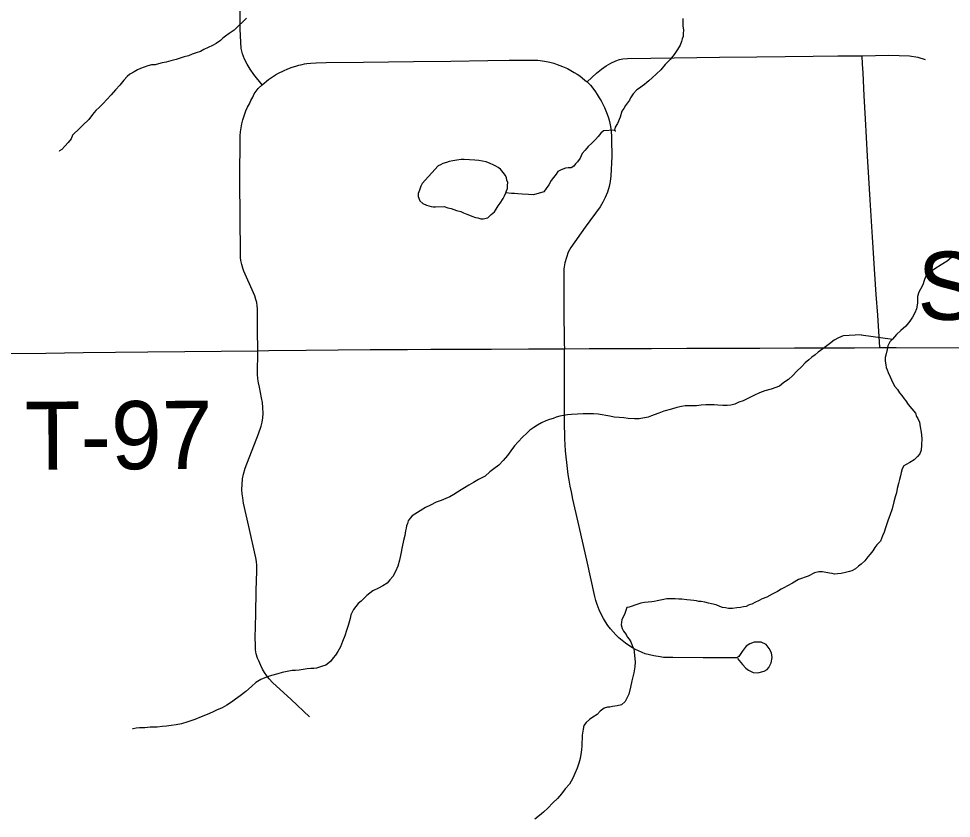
# Model space of a CAD drawing. Extents: x 103424 to 286016, y 38711 to 110967.
# Drawn here: x 108708 to 112838, y 81319 to 84863 of the extents above; entities that cross this region are included whole.
import ezdxf

# ---------------------------------------------------------------- set-up
doc = ezdxf.new("R2010")
doc.units = 0
for name, color, linetype in [('GM_X_Minor_Lake', 7, 'Continuous'), ('GM_X_Minor_River', 7, 'Continuous'), ('GM_X_Township_Road', 7, 'Continuous'), ('GM_X_Township_Road_Text', 7, 'Continuous')]:
    doc.layers.add(name, color=color, linetype=linetype)

msp = doc.modelspace()

# ---------------------------------------------------------------- linework, layer by layer
at = {"layer": 'GM_X_Minor_Lake'}
for points in [[(110495, 84132.8), (110488.3, 84120.7), (110482.5, 84102.5), (110476.6, 84088.3), (110476.7, 84074.1), (110485, 84056), (110497.3, 84044.1), (110513.5, 84036.1), (110533.8, 84030.3), (110543.9, 84028.4), (110554, 84028.4), (110592.4, 84030.9), (110608.6, 84025), (110622.8, 84021.1), (110634.9, 84017.1), (110647.1, 84013.2), (110665.3, 84007.3), (110677.5, 84001.4), (110691.7, 83995.5), (110703.9, 83991.6), (110714, 83987.6), (110730.3, 83981.7), (110740.4, 83979.8), (110754.6, 83975.9), (110764.7, 83976), (110784.8, 83980.3), (110800.8, 83994.6), (110814.8, 84006.8), (110822.7, 84019), (110830.6, 84033.3), (110840.6, 84045.5), (110852.5, 84065.8), (110858.4, 84078), (110864.3, 84090.2), (110868.2, 84100.3), (110872.2, 84110.4), (110872, 84122.5), (110873.9, 84136.7), (110869.7, 84146.8), (110867.6, 84156.8), (110863.4, 84166.9), (110853.2, 84180.9), (110840.9, 84195), (110830.7, 84202.9), (110820.5, 84208.9), (110808.3, 84214.8), (110796.2, 84220.8), (110777.9, 84228.7), (110761.7, 84230.5), (110745.5, 84234.4), (110727.3, 84236.2), (110680.8, 84237.8), (110666.7, 84237.7), (110648.5, 84235.5), (110630.4, 84233.2), (110614.3, 84229.1), (110602.2, 84224.9), (110586.1, 84220.7), (110576.1, 84214.5), (110566, 84210.4), (110495, 84132.8)], [(110840.6, 84045.5), (110852.5, 84065.8), (110858.4, 84078), (110864.3, 84090.2), (110868.2, 84100.3), (110872.2, 84110.4), (110872, 84122.5), (110873.9, 84136.7), (110869.7, 84146.8), (110867.6, 84156.8), (110863.4, 84166.9), (110853.2, 84180.9), (110840.9, 84195), (110830.7, 84202.9), (110820.5, 84208.9), (110808.3, 84214.8), (110796.2, 84220.8), (110777.9, 84228.7), (110761.7, 84230.5), (110745.5, 84234.4), (110727.3, 84236.2), (110680.8, 84237.8), (110666.7, 84237.7), (110648.5, 84235.5), (110630.4, 84233.2), (110614.3, 84229.1), (110602.2, 84224.9), (110586.1, 84220.7), (110576.1, 84214.5), (110566, 84210.4), (110495, 84132.8)], [(110495, 84132.8), (110488.3, 84120.7), (110482.5, 84102.5), (110476.6, 84088.3), (110476.7, 84074.1), (110485, 84056), (110497.3, 84044.1), (110513.5, 84036.1), (110533.8, 84030.3), (110543.9, 84028.4), (110554, 84028.4), (110592.4, 84030.9), (110608.6, 84025), (110622.8, 84021.1), (110634.9, 84017.1), (110647.1, 84013.2), (110665.3, 84007.3), (110677.5, 84001.4), (110691.7, 83995.5), (110703.9, 83991.6), (110714, 83987.6), (110730.3, 83981.7), (110740.4, 83979.8), (110754.6, 83975.9), (110764.7, 83976), (110784.8, 83980.3), (110800.8, 83994.6), (110814.8, 84006.8), (110822.7, 84019), (110830.6, 84033.3), (110840.6, 84045.5)]]:
    msp.add_lwpolyline(points, dxfattribs=at)
at = {"layer": 'GM_X_Minor_River'}
for points in [[(109716.2, 84864.5), (109700.2, 84848.1), (109682.3, 84831.8)], [(111649, 84863.6), (111649.2, 84847.5), (111649.4, 84831.3), (111651.7, 84811.1), (111649.8, 84797), (111650, 84782.8), (111646.1, 84772.7), (111642.2, 84760.5), (111636.3, 84744.3), (111624.4, 84726), (111610.5, 84703.6), (111592.6, 84681.3), (111570.6, 84658.8), (111550.7, 84636.4), (111532.7, 84618), (111512.8, 84599.7), (111498.8, 84587.4), (111488.8, 84579.2), (111478.8, 84571), (111468.8, 84562.8), (111456.7, 84554.6), (111444.7, 84546.4), (111428.7, 84530.1), (111416.8, 84511.8), (111412.9, 84501.7), (111403, 84489.5), (111395, 84477.3), (111387.1, 84465.1), (111379.2, 84452.9), (111371.4, 84426.5), (111359.6, 84398.1), (111349.7, 84381.9), (111345.8, 84367.7), (111349.9, 84365.7), (111351.9, 84365.7)], [(109682.3, 84831.8), (109662.3, 84811.4), (109640.2, 84797), (109624.2, 84784.8), (109612.2, 84776.6), (109602.2, 84766.4), (109582.2, 84752), (109566.1, 84743.8), (109528, 84725.2), (109513.9, 84717), (109493.8, 84710.7), (109475.7, 84704.5), (109459.6, 84698.3), (109441.5, 84694), (109423.4, 84687.8), (109405.3, 84681.6), (109381.1, 84675.3), (109361, 84669), (109342.9, 84666.8), (109326.8, 84662.6), (109312.7, 84658.4), (109296.5, 84658.2), (109280.4, 84654), (109264.3, 84647.8), (109248.2, 84641.6), (109234.2, 84635.4), (109220.1, 84627.2), (109200, 84616.9), (109188, 84606.7), (109174.1, 84590.4), (109156.2, 84568), (109136.2, 84547.6), (109118.3, 84525.2), (109098.3, 84504.8), (109082.4, 84486.4), (109066.4, 84470.1), (109050.4, 84455.8), (109034.5, 84437.5), (109018.6, 84415.1), (108992.6, 84390.6), (108970.7, 84368.1), (108954.7, 84355.8), (108946.7, 84345.7), (108940.8, 84329.4), (108926.9, 84313.2), (108912.9, 84296.8), (108899, 84282.6), (108888.9, 84276.4), (108886.9, 84274.4)], [(111345.8, 84367.7), (111297.4, 84365.2), (111285.4, 84355), (111273.4, 84340.7), (111261.5, 84326.4), (111245.5, 84310.1), (111229.5, 84295.8), (111215.6, 84279.5), (111203.6, 84265.3), (111193.7, 84245), (111181.8, 84228.7), (111173.9, 84218.5), (111165.9, 84208.3), (111153.8, 84202.1), (111141.7, 84202), (111129.6, 84199.9), (111117.6, 84195.7), (111107.5, 84191.6), (111095.5, 84185.4), (111087.5, 84173.2), (111075.6, 84158.9), (111065.7, 84144.7), (111055.8, 84126.4), (111043.8, 84110.1), (111033.9, 84095.9), (110987.6, 84081.3), (110965.4, 84083.1), (110937.1, 84084.8), (110918.9, 84086.7), (110902.7, 84088.5), (110890.6, 84088.4), (110864.3, 84090.2)], [(112838.8, 83804.9), (112818.8, 83788.5), (112792.7, 83772.1), (112764.7, 83753.6), (112744.6, 83741.3), (112728.6, 83731.1), (112722.7, 83718.9), (112716.8, 83702.7), (112711, 83682.4), (112701.1, 83664.1), (112693.2, 83649.9), (112687.3, 83631.7), (112687.4, 83621.6), (112687.7, 83601.4), (112683.9, 83577.1), (112676.1, 83558.8), (112666.2, 83540.5), (112654.3, 83522.2), (112636.4, 83499.8), (112614.3, 83481.4), (112594.4, 83463.1), (112576.4, 83442.7), (112564.5, 83430.5), (112556.6, 83412.2), (112552.7, 83396), (112548.9, 83377.8), (112545.1, 83361.6), (112545.2, 83345.4), (112547.5, 83329.3), (112549.6, 83317.2), (112553.8, 83307.1), (112557.9, 83295), (112566.3, 83274.9), (112572.5, 83262.9), (112578.7, 83248.8), (112586.9, 83232.7), (112599.2, 83218.7), (112607.5, 83204.6), (112617.7, 83192.6), (112628, 83178.6), (112636.2, 83168.5), (112646.5, 83152.5), (112679.2, 83114.4), (112683.4, 83100.3), (112689.6, 83090.3), (112695.8, 83074.2), (112700.1, 83054.1), (112704.4, 83029.9), (112706.8, 83001.6), (112705.1, 82973.3), (112703.3, 82951.1), (112697.5, 82934.8), (112687.5, 82922.6), (112673.5, 82908.3), (112653.5, 82896), (112637.4, 82887.8), (112627.4, 82881.6), (112619.5, 82867.4), (112615.6, 82851.2), (112611.7, 82837), (112607.9, 82820.8), (112604.1, 82802.6), (112598.3, 82780.3), (112594.4, 82762.1), (112588.6, 82743.9), (112582.8, 82721.6), (112575.1, 82691.2), (112565.3, 82660.8), (112557.5, 82642.5), (112551.6, 82624.3), (112545.8, 82606.1), (112539.9, 82587.8), (112532, 82571.6), (112524.2, 82547.3), (112508.3, 82531)], [(112438.9, 83461.5), (112358.1, 83456.7), (112338, 83448.4), (112318, 83438.1), (112298, 83421.7), (112267.9, 83399.2), (112247.9, 83384.9), (112233.9, 83372.6), (112219.9, 83362.3), (112205.9, 83350.1), (112189.9, 83337.8), (112173.9, 83319.5), (112154, 83301.1), (112136, 83280.7), (112116, 83264.4), (112096, 83250), (112076, 83233.7), (112039.8, 83221.2), (112011.6, 83212.8), (111987.4, 83204.5), (111963.4, 83192.1), (111937.2, 83179.7), (111915.1, 83169.4), (111897, 83163.2), (111879, 83154.9), (111860.8, 83150.7), (111844.7, 83148.5), (111826.5, 83148.3), (111804.3, 83150.1), (111788.1, 83152), (111769.9, 83151.8), (111749.8, 83151.6), (111729.6, 83149.4), (111709.4, 83147.2), (111691.2, 83147), (111675.1, 83146.8), (111658.9, 83146.7), (111642.8, 83144.5), (111622.6, 83140.2), (111598.5, 83131.9), (111564.3, 83123.5), (111542.1, 83115.2), (111522.1, 83106.9), (111510, 83102.7), (111495.9, 83096.5), (111455.6, 83090.1), (111435.4, 83089.9), (111407.1, 83091.6), (111386.9, 83093.4), (111366.7, 83095.2), (111344.4, 83097), (111326.2, 83100.9), (111308, 83104.8), (111291.8, 83106.6), (111273.6, 83110.5), (111253.4, 83112.3), (111231.2, 83112.1), (111206.9, 83111.8), (111182.7, 83109.6), (111156.5, 83109.3), (111138.3, 83107.1), (111120.2, 83104.9), (111104.1, 83100.7), (111088, 83096.5), (111073.9, 83090.3), (111057.8, 83086.1), (111041.7, 83079.9), (111023.6, 83071.6), (111005.6, 83061.3), (110989.5, 83051.1), (110971.5, 83038.8), (110957.5, 83026.5), (110939.5, 83008.1), (110919.6, 82987.7), (110903.6, 82969.4), (110887.7, 82947), (110871.8, 82926.7), (110853.9, 82904.3), (110833.9, 82883.9), (110811.9, 82867.5), (110793.9, 82855.2), (110773.9, 82834.8), (110743.8, 82820.3), (110721.7, 82808), (110701.7, 82795.7), (110681.6, 82783.3), (110667.6, 82775.1), (110651.5, 82764.9), (110635.5, 82754.6), (110617.4, 82744.3), (110599.4, 82736.1), (110579.2, 82727.8), (110557.1, 82719.5), (110531, 82707.1)], [(112438.9, 83461.5), (112576.4, 83442.7)], [(110531, 82707.1), (110508.9, 82696.8), (110450.8, 82659.8), (110440.8, 82649.6), (110432.9, 82637.4), (110429, 82625.3), (110425, 82615.1), (110423.1, 82605), (110421.3, 82592.9), (110417.5, 82572.6), (110411.7, 82550.4), (110405.9, 82522), (110400.2, 82491.7), (110394.5, 82463.3), (110386.7, 82437), (110376.9, 82412.7), (110365, 82390.3), (110351.1, 82376), (110339.1, 82361.8), (110321.1, 82349.5), (110301, 82339.2), (110276.9, 82326.8), (110262.9, 82316.6), (110248.9, 82306.3), (110238.9, 82296.1), (110224.9, 82281.8), (110210.9, 82271.6), (110201, 82257.4), (110191, 82245.2), (110185.1, 82233), (110179.2, 82220.8), (110175.3, 82204.6), (110167.6, 82174.2), (110159.8, 82151.9), (110152, 82127.6), (110142.2, 82103.3), (110132.4, 82078.9), (110120.5, 82058.6), (110110.6, 82042.3), (110100.6, 82030.1), (110088.7, 82013.8), (110068.7, 81997.5), (110052.6, 81993.3), (110026.4, 81984.9), (110014.3, 81982.8), (110002.2, 81982.7), (109986.1, 81982.5), (109967.9, 81978.3), (109949.8, 81976.1), (109933.6, 81973.9), (109919.5, 81973.8), (109875.2, 81965.2), (109855.1, 81959), (109826.9, 81952.6), (109804.7, 81944.3), (109780.6, 81934), (109758.5, 81921.6), (109738.6, 81903.3), (109714.6, 81880.8), (109688.5, 81862.4), (109668.5, 81848), (109650.5, 81833.7), (109630.4, 81821.4), (109608.4, 81809), (109584.3, 81798.7), (109566.2, 81790.5), (109542.1, 81780.1), (109515.9, 81769.7), (109487.8, 81757.3), (109457.6, 81746.9), (109429.4, 81738.6), (109405.3, 81734.3), (109383.1, 81730), (109362.9, 81727.8), (109342.8, 81725.6), (109320.6, 81723.3), (109290.3, 81723), (109266.1, 81720.8), (109243.8, 81720.6), (109227.7, 81718.4), (109215.6, 81716.2), (109211.6, 81716.2)], [(112508.3, 82531), (112498.3, 82518.7), (112490.4, 82504.5), (112478.5, 82490.3), (112468.5, 82478), (112454.6, 82459.7), (112438.6, 82445.4), (112426.6, 82437.2), (112412.6, 82425), (112396.5, 82416.7), (112386.5, 82412.6), (112368.3, 82408.4), (112350.2, 82404.1), (112334.1, 82402), (112319.9, 82401.8), (112309.8, 82403.7), (112297.7, 82405.6), (112267.3, 82411.4), (112251.2, 82411.2), (112231, 82407), (112202.9, 82392.6), (112160.7, 82378), (112134.6, 82361.6), (112112.5, 82349.2), (112096.5, 82341), (112084.4, 82334.8), (112068.4, 82324.5), (112044.3, 82312.2), (112020.2, 82299.8), (112000.1, 82291.5), (111984, 82283.3), (111970, 82277.1), (111953.9, 82268.9), (111941.8, 82264.7), (111929.8, 82258.5), (111917.7, 82256.4), (111903.6, 82254.2), (111887.5, 82252), (111869.3, 82249.8), (111851.1, 82249.7), (111837, 82251.5), (111824.8, 82253.4), (111812.7, 82257.3), (111796.4, 82265.3), (111776.2, 82269.1), (111762, 82273), (111745.8, 82276.9), (111729.6, 82280.8), (111719.5, 82280.7), (111709.4, 82282.6), (111697.2, 82284.5), (111683.1, 82286.3), (111666.9, 82288.2), (111644.7, 82290), (111630.5, 82289.9), (111614.3, 82291.7), (111596.2, 82291.5), (111578, 82291.4), (111557.9, 82287.1), (111535.7, 82282.9), (111521.6, 82280.7), (111511.5, 82278.6), (111479.2, 82276.2), (111463.1, 82272), (111449, 82267.8), (111436.9, 82263.7), (111424.9, 82259.5), (111410.8, 82255.3), (111400.7, 82253.2), (111391, 82222.8), (111379.1, 82200.5), (111375.4, 82176.2), (111379.6, 82160.1), (111385.8, 82148), (111398.1, 82134), (111402.2, 82124), (111410.4, 82113.9), (111418.6, 82101.9), (111424.9, 82085.8), (111431.1, 82069.7), (111437.8, 82013.2), (111436.1, 81991), (111432.3, 81964.7), (111422.7, 81928.2), (111416.9, 81899.9), (111409.2, 81869.5), (111399.4, 81849.2), (111393.4, 81837), (111377.4, 81822.7), (111357.3, 81818.5), (111337.2, 81814.2), (111325.1, 81812.1), (111315, 81812), (111300.9, 81807.8), (111282.9, 81793.5), (111268.9, 81779.2), (111250.9, 81766.9), (111234.8, 81756.7), (111220.8, 81744.4), (111210.9, 81730.1), (111207, 81713.9)], [(111207, 81713.9), (111203.3, 81687.7), (111201.8, 81641.2), (111200, 81623), (111198.1, 81612.9), (111194.4, 81584.5), (111188.6, 81564.3), (111180.8, 81542), (111170.9, 81517.7), (111161.1, 81497.4), (111147.2, 81470.9), (111127.3, 81450.6), (111111.4, 81428.2), (111093.5, 81407.8), (111073.5, 81387.4), (111051.5, 81364.9), (111031.6, 81346.6), (111013.6, 81332.3), (110993.5, 81315.9)]]:
    msp.add_lwpolyline(points, dxfattribs=at)
at = {"layer": 'GM_X_Township_Road'}
for points in [[(109785.6, 84569.9), (109748.8, 84615.5), (109733, 84639.1), (109719.4, 84660.4), (109708.6, 84683.1), (109698.4, 84706.6), (109693.7, 84730.7), (109691.5, 84757.8), (109688.5, 84816), (109688.9, 84970.8), (109689.1, 85045.5)], [(111224.6, 84582), (111266.9, 84621.4), (111288.2, 84639), (111309.8, 84653.6), (111329.4, 84664.8), (111352.4, 84675), (111367.6, 84680.8), (111382.7, 84683.8), (111404.4, 84686), (111507.3, 84687.3), (111610.1, 84688.5), (111710.8, 84690.1), (111811.6, 84691.7), (111976.6, 84693.6), (112101.4, 84695.1), (112226.2, 84696.6), (112334.3, 84697.5), (112442.3, 84698.3), (112560.1, 84700.1), (112652.7, 84698.3), (112689.7, 84692.4), (112721, 84681.1)], [(112520.4, 83405.2), (112511.5, 83549.2), (112504.9, 83639.7), (112498.3, 83730.3), (112488.3, 83895), (112478.3, 84059.8), (112472.4, 84156.5), (112466.6, 84253.1), (112457.6, 84418), (112452, 84520), (112446.5, 84622.1), (112444, 84661.1), (112442.3, 84698.3)], [(109766.5, 83391.3), (109766, 83483.9), (109765.5, 83576.5), (109764.2, 83590.5), (109761.9, 83604.4), (109758.9, 83618.1), (109753.7, 83634.8), (109748.4, 83647.9), (109705.6, 83743.8), (109700.6, 83756.9), (109695.6, 83773.8), (109692.1, 83791), (109690.6, 83804.9), (109689.8, 83821.5), (109688.5, 83982.4), (109687.2, 84143.3), (109688.3, 84343.4), (109690, 84361.2), (109692.6, 84379), (109696.1, 84396.6), (109700.4, 84413.9), (109707.7, 84436.7), (109714.3, 84453.4), (109721.6, 84469.7), (109729.9, 84485.7), (109736.2, 84500.5), (109744.5, 84514.4), (109751.4, 84529.2), (109759.7, 84541.3), (109767.9, 84552.6), (109785.6, 84569.9), (109813.9, 84593), (109832.1, 84605.1), (109845.6, 84613.4), (109859, 84620.3), (109880.8, 84632), (109899.8, 84640.7), (109918.5, 84647.2), (109935.4, 84652.4), (109948.9, 84655.9), (109963.2, 84659.4), (109973.6, 84662), (109984.1, 84663.7), (110001, 84665.4), (110025.3, 84666.4), (110069.1, 84668.1), (110234.2, 84670.1), (110345, 84671.5), (110455.8, 84672.8), (110620.9, 84674.8), (110785.9, 84676.7), (110879.3, 84677.8), (110972.7, 84678.9), (111007, 84678.5), (111027, 84675.9), (111044.8, 84672.4), (111060.4, 84669.3), (111077.3, 84664.6), (111091.6, 84659.8), (111116.4, 84650.7), (111137.6, 84641.2), (111152.8, 84633.3), (111167.6, 84624.6), (111180.2, 84616), (111192.3, 84609), (111214.9, 84590.4), (111224.6, 84582), (111239.2, 84567.4), (111250.5, 84554.4), (111261.3, 84538.3), (111269.7, 84525.7), (111278.8, 84512.1), (111287.1, 84498.1), (111294.9, 84483.7), (111301.9, 84469.1), (111308.5, 84454), (111314, 84438.7), (111319, 84423.2), (111323.3, 84407.5), (111326.8, 84391.5), (111329.6, 84375.4), (111331.6, 84359.2), (111332.8, 84342.9), (111333.3, 84326.6), (111334.3, 84251.8), (111330.3, 84166.4), (111327.3, 84140.3), (111322.1, 84118.6), (111314.7, 84093.9), (111304.3, 84070), (111294.7, 84050), (111282.2, 84029), (111216.2, 83938.5), (111153.3, 83849.1), (111141.6, 83827.4), (111132.9, 83803.9), (111126.8, 83780.5), (111121.6, 83754.5), (111121.1, 83727.1), (111122.4, 83575.5), (111123.7, 83423.8), (111124.2, 83399.6)], [(108663.4, 83378.7), (108828.4, 83380.6), (108993.5, 83382.6), (109136.4, 83384.3), (109279.3, 83386), (109444.3, 83387.8), (109605.4, 83389.6), (109766.5, 83391.3), (109815.6, 83391.9), (109980.7, 83393.6), (110122.3, 83395), (110264, 83396.4), (110429.1, 83397), (110533, 83397.4), (110636.8, 83397.8), (110800.9, 83398.4), (110964.9, 83399), (111124.2, 83399.6), (111234.3, 83400.5), (111344.3, 83401.2), (111509.4, 83401.7), (111666.9, 83402.1), (111824.4, 83402.5), (111989.5, 83402.9), (112142.8, 83403.4), (112296.2, 83403.8), (112408.3, 83404.5), (112520.4, 83405.2), (112593.1, 83405.7), (113939.6, 83404.7)], [(109996.2, 81769.8), (109914.3, 81845.6), (109832.4, 81921.4), (109817.6, 81937.4), (109806.5, 81951.2), (109796.4, 81965.7), (109787.7, 81980.8), (109779.8, 81996.5), (109771.6, 82016.8), (109765.6, 82029.2), (109760.2, 82047.8), (109757.2, 82066), (109756.1, 82088.9), (109755.5, 82118.3), (109757.7, 82223.8), (109759.9, 82329.2), (109763.2, 82415), (109762.5, 82439.9), (109760.9, 82457.1), (109758.1, 82474), (109727.6, 82612.8), (109703.1, 82716), (109699.9, 82740), (109697.9, 82757.5), (109696.9, 82775), (109699.1, 82824.3), (109703.1, 82844.3), (109711.6, 82870.3), (109770, 83022.8), (109781.5, 83056.6), (109785.8, 83075.1), (109789.5, 83093.3), (109790.9, 83113.6), (109789.2, 83139.2), (109787.5, 83162.5), (109783.8, 83182.4), (109773.9, 83230.2), (109769.3, 83248.6), (109767.3, 83266.8), (109765.9, 83287.4), (109766.5, 83391.3)], [(111891.1, 82027.9), (111912.6, 82001.5), (111926.9, 81984.1), (111939.4, 81975.6), (111960.7, 81965.8), (111980.4, 81963.6), (112008.9, 81971.2), (112021.4, 81978.7), (112029.8, 81987.6), (112039.6, 82008.1), (112044.5, 82031.3), (112041.8, 82053.1), (112031.2, 82072.3), (112017.8, 82089.7), (111995.5, 82099.5), (111965.2, 82100.4), (111945.2, 82093.2), (111928.7, 82082.1), (111911.7, 82058), (111896.6, 82036.7), (111888.4, 82030.8), (111871.8, 82030), (111738.3, 82030.6), (111604.7, 82031.3), (111562.4, 82032.2), (111547.7, 82034.9), (111520.1, 82039.8), (111482.4, 82048.7), (111468.4, 82054.2), (111449.2, 82062.9), (111441.5, 82066.6), (111425.2, 82075.4), (111409.6, 82085.2), (111394.5, 82095.7), (111379.9, 82107), (111365.8, 82119.1), (111352.4, 82131.9), (111339.9, 82145.3), (111328, 82159.4), (111317, 82174.1), (111306.4, 82189.3), (111296.9, 82205.2), (111288.3, 82221.4), (111278, 82243.7), (111269.2, 82266.8), (111263.9, 82284.4), (111259.4, 82302.3), (111223.1, 82463.3), (111204.1, 82547.4), (111185.1, 82631.5), (111162.2, 82733.3), (111155.4, 82765.3), (111150.4, 82791.1), (111145.8, 82817.1), (111141.6, 82843.2), (111138.1, 82869.2), (111134.8, 82895.4), (111132, 82921.6), (111129.8, 82947.9), (111128.1, 82974.2), (111126.6, 83000.5), (111125.8, 83026.9), (111125.3, 83053.2), (111125, 83166.8), (111124.6, 83280.3), (111124.2, 83399.6)]]:
    msp.add_lwpolyline(points, dxfattribs=at)

# ---------------------------------------------------------------- texts
at = {"layer": 'GM_X_Township_Road_Text'}
for s, rotation, p in [('SHERMAN', 0, (112687.2, 83528.1)), ('T-97', 0.3535, (108736.7, 82863.2))]:
    msp.add_text(s, height=301.87, rotation=rotation, dxfattribs=at).set_placement(p)

doc.saveas('drawing.dxf')
